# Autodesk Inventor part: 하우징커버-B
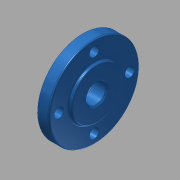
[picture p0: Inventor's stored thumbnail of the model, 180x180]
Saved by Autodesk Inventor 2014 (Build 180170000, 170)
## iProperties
Created: 2018-01
Part Number: 하우징커버-B
Material: 알루미늄 6061
Document SubType Name: Modeling
Designer: mduedu
Density: 1 g/cm^3
Appearance: 청록색
Author: mduedu
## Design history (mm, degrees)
sketch "스케치1"
  geometry: C1 r 16 at (0, 0); 1 further point
  constraints: 1 centre point, 1 coincident
  dimensions: "d0" = 32 diameter of C1
extrude "돌출1" new body sketch "스케치1" distance "d1" = 4; taper "d2" = 0 deg
sketch "스케치2"
  geometry: C1 r 9 at (0, 0); 1 further point
  constraints: 1 centre point, 1 coincident
  dimensions: "d3" = 18 diameter of C1
extrude "돌출2" join sketch "스케치2" distance "d4" = 1; taper "d5" = 0 deg
fillet "모깎기1" dims "d6" = 0.5
fillet "모깎기2" dims "d7" = 0.5
hole "구멍1" diameter "d10" = 7; stored, may be unused: countersink angle "d14" = 90 deg, drill point angle "d16" = 118 deg; dims "d8" = 10, "d9" = 10, "d11" = 6, "d12" = 4, "d13" = 2, "d15" = 8
chamfer "모따기1" distance "d17" = 0.5; stored, may be unused: second distance "d18" = 2, angle "d19" = 45 deg
sketch "스케치3" dims "d21" = 25
  geometry: 6 further points
  constraints: 2 vertical alignment, 1 coincident, 7 other
  dimensions: "d24" = 360 deg dimension on point (0, 0) point (0, 12.5) (derived)
sketch "스케치4"
  geometry: 4 further points
  constraints: 4 other
hole "구멍2" sketch "스케치4" at (-12.5, 0), (0, -12.5), (12.5, 0), (0, 12.5) diameter "d26" = 3.4; stored, may be unused: countersink angle "d30" = 90 deg, drill point angle "d32" = 0 deg; dims "d27" = 6, "d28" = 4, "d29" = 2, "d31" = 8
node "솔리드1"
